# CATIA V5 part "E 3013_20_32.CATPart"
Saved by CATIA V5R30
Part number: Vodici_vlozka_slideru
Definition: E 3013_20_32
Nomenclature: E 3013_20_32
Source: Unknown
Description: PART-E 3013_20_32-DESC
Bounding box of the stored display mesh (mm): x 56 to 102, y -20.5 to 20.5, z 0 to 20
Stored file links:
  E:\Bakalarka\Model\Forma_v7\E 3013_20_32.CATPart
  E:\Bakalarka\Model\Sestava_formy_sliderky\Copy (1) of E 3014_20_32.CATProduct
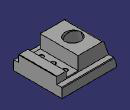
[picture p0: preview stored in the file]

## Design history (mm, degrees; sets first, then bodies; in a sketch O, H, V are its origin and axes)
Body1 "MANIFOLD_SOLID_BREP #127" (main body)
  Solid1: solid without history
  Body2 "Result of TapHole"
    Solid2: linked copy from another document
  Assemble1 "TapHoleCapScrew_E1200_1.1": tool Body2
  Body3 "Result of TapHole"
    Solid3: linked copy from another document
  Assemble2 "TapHoleCapScrew_E1200_1.2": tool Body3
  DatumCurve1
  DatumCurve2
  Sketch1 on zx-plane, origin (0, 0, 0), H (-1, 0, 0), V (0, 0, 1)
    projected line E1 (-76.2948, 1.8) -> (-76.2948, 0) from edge of DatumCurve1
    point P1 (-76.2948, 1.8)
    point P2 (-76.2948, 0)
    construction line L1 (-76.2948, 0) -> (-78.6948, 0)
    point P3 (-76.2948, 0)
    point P4 (-78.6948, 0)
    construction arc A1 centre (-76.2948, -0.7) radius 2.5 from (-76.2948, 1.8) to (-78.6948, 0) ccw
    point P6 (-78.6948, 0)
    point P7 (-76.2948, 1.8)
    line L2 (-86.4, 0) -> (-84, 0)
    line L3 (-84, 0) -> (-84, 1.8)
    point P10 (-84, 1.8)
    arc A2 centre (-84, -0.7) radius 2.5 from (-84, 1.8) to (-86.4, 0) ccw
    point P12 (-84, 1.8)
    reference projected line E2 (-56, 0) -> (-102, 0) from edge [face of Solid1 | face of Solid1]
    reference projected line E3 (-102, 7.5) -> (-102, 0) from edge [face of Solid1 | face of Solid1]
    distance P1 P7 = 0
    distance P6 P4 = 0
    length L1 = 2.4
    distance P3 P2 = 0
    radius A1 = 2.5
    distance P12 P10 = 0
    distance L2 E2 = 0
    length L3 = 1.8
    length L2 = 2.4
    distance L3 E3 = 18
    radius A2 = 2.5
    coincidence: P3 H, P6 H
    horizontal: L1 H, L2 H
    vertical: L3 V
  Groove1: profile Sketch1, axis Sketch1.L3, angle 360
